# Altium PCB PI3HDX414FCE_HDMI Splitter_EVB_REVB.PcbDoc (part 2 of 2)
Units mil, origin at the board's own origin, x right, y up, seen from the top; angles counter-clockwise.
Board outline 3885 x 4772 mil, 4 copper layers (Top Layer, InternalPlane1, InternalPlane2, Bottom Layer); 85 components, 103 nets, 428 pads, 187 vias.
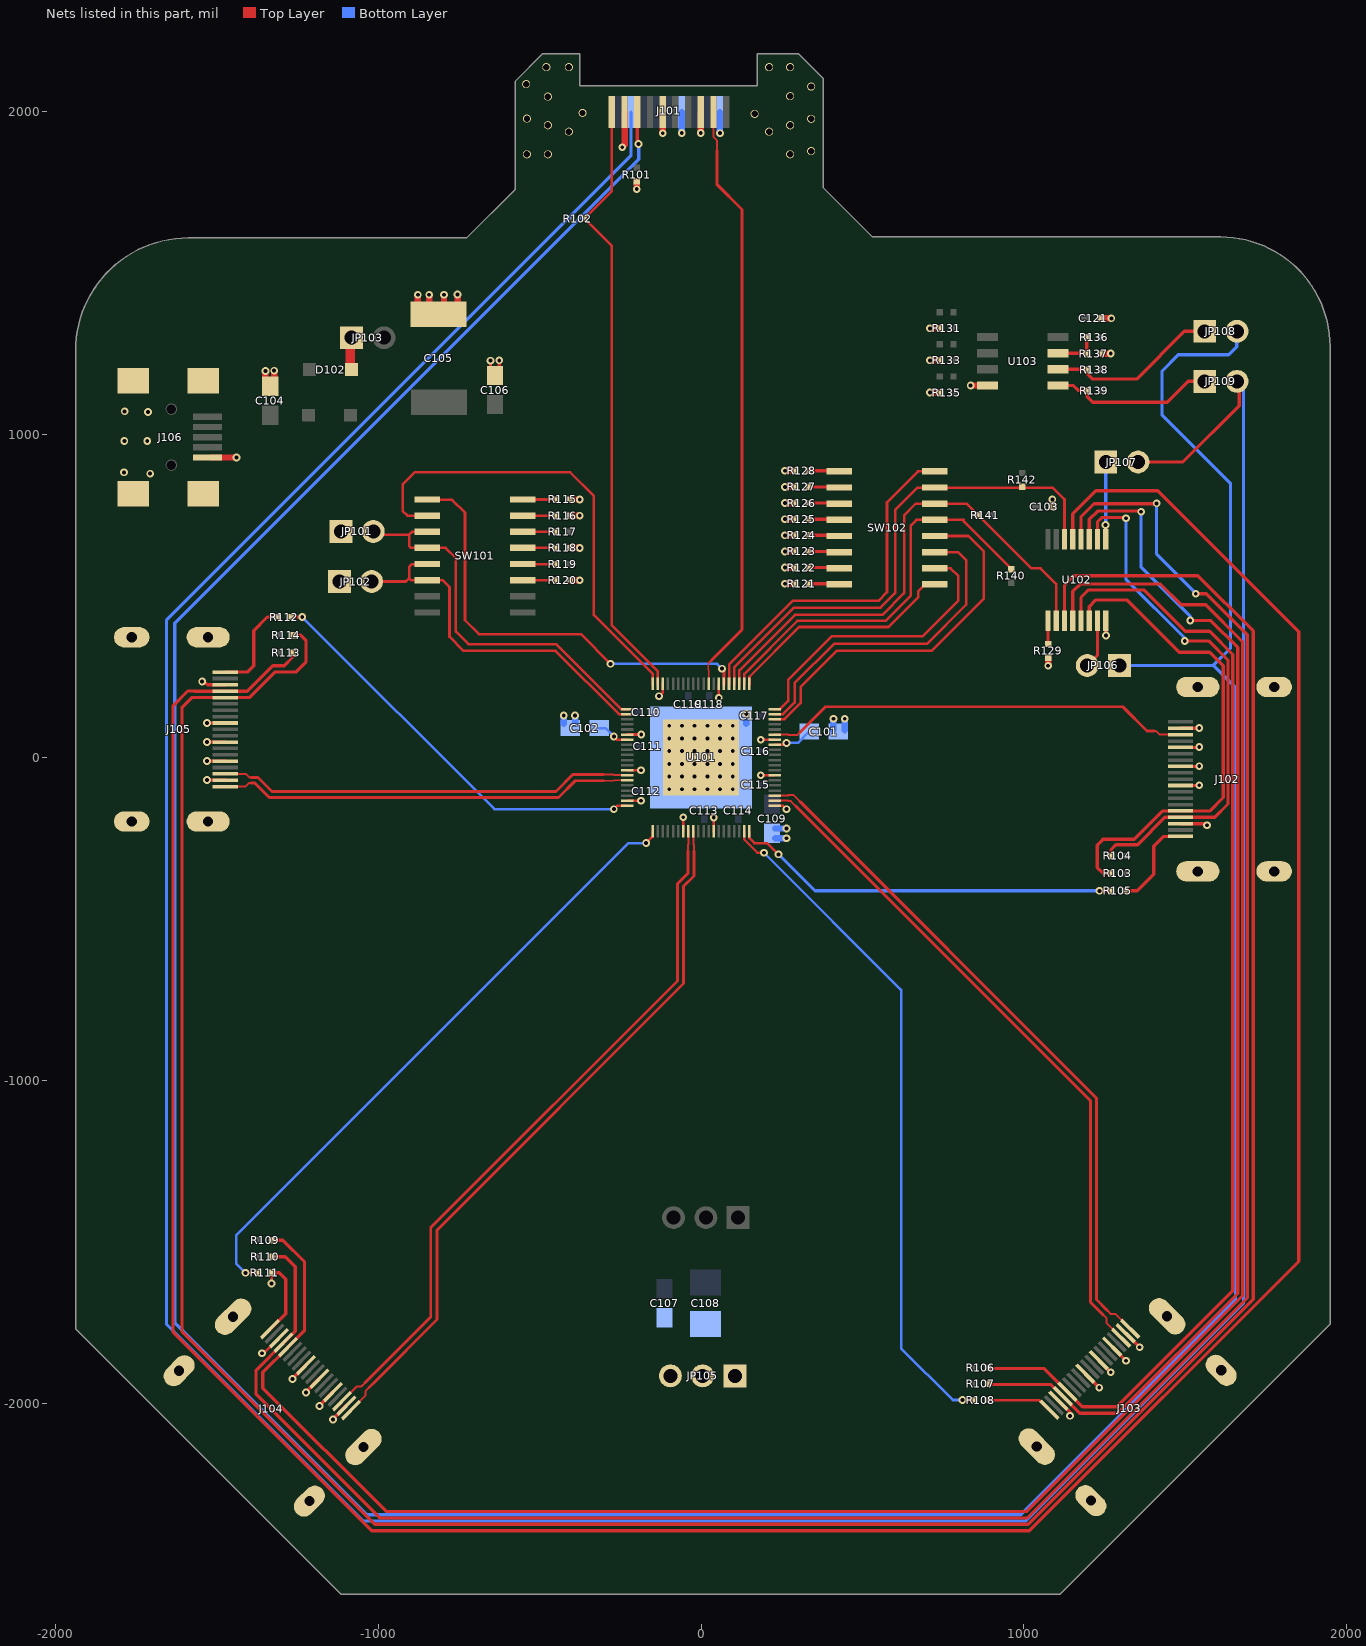
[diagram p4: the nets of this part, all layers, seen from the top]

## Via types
v1: diameter 24, hole 12, Top Layer to Bottom Layer, tented both sides, 186 vias
v2: diameter 35, hole 20, Top Layer to Bottom Layer, tented both sides, 1 vias

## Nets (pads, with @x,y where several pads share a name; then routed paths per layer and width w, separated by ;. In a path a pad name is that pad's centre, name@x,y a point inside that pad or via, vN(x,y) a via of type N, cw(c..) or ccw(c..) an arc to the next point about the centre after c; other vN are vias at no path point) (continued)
D2+_2: J103.1 U101.43 | length 2155.2
  Top Layer w6: U101.43@224.82,-117.72 228.35,-117.72 269.82,-117.72 271.44,-116.09 285.96,-116.09 307.04,-137.17 ; 1258.32,-1712.34 1269.71,-1723.73 1283.73,-1723.73 J103.1@1329.18,-1769.18
  Top Layer w9: 307.04,-137.17 1225,-1055.13 1225,-1679.02 1258.32,-1712.33
D2+_3: J104.1 U101.29 | length 2238
  Top Layer w6: J104.1@-1084.18,-2021.18 -1038.73,-1975.73 -1038.73,-1961.71 -1027.98,-1950.96 ; U101.29@-23.21,-224.02 -23.21,-228.35 -23.21,-269.02 -21.59,-270.64 -21.59,-289
  Top Layer w9: -1027.98,-1950.96 -1007.01,-1929.99 -818,-1740.98 -818,-1463.87 -54,-699.87 -54,-399 -21.59,-366.59 -21.59,-289
D2+_4: J105.1 U101.15 | length 1294.5
  Top Layer w6: J105.1@-1472.94,-90 -1411,-90 -1399.82,-78.82 -1394,-78.82 ; -302.23,-72.1 -270.63,-72.1 -269,-70.47 -228.35,-70.47 U101.15@-224,-70.47
  Top Layer w9: -1394,-78.82 -1382.05,-78.82 -1336.87,-124 -441.13,-124 -389.23,-72.1 -302.23,-72.1
D2-: J101.3 U101.69 | length 1846.1
  Top Layer w6: U101.69@24.03,224.8 24.03,228.35 24.03,269.8 22.41,271.43 22.41,291.28 32.03,300.9 ; J101.3@38,1990 38,1921.98 48.98,1911 48.98,1879
  Top Layer w9: 32.03,300.9 127,395.87 127,1697.13 48.98,1775.15 48.98,1879
D2-_1: J102.3 U101.55 | length 1332.8
  Top Layer w6: U101.55@224.82,71.26 228.35,71.26 269.82,71.26 271.44,69.63 298.5,69.63 305.96,77.09 ; 1403,81.81 1409.19,81.81 1420.37,70.63 J102.3@1484.94,70.63
  Top Layer w9: 305.96,77.09 385.87,157 1306.13,157 1381.32,81.81 1403,81.81
D2-_2: J103.3 U101.42 | length 2137.6
  Top Layer w6: U101.42@224.82,-133.46 228.35,-133.46 269.82,-133.46 271.44,-135.09 278.09,-135.09 293.61,-150.61 ; 1245.57,-1726.46 1256.05,-1736.93 1256.05,-1751.73 J103.3@1301.34,-1797.02
  Top Layer w9: 293.61,-150.61 1206,-1063 1206,-1686.89 1234.06,-1714.94 ; 1235.56,-1716.44 1245.57,-1726.46
D2-_3: J104.3 U101.28 | length 2222.5
  Top Layer w6: J104.3@-1112.02,-1993.34 -1066.73,-1948.05 -1051.93,-1948.05 -1040.45,-1936.56 ; -40.59,-290 -40.59,-270.64 -38.96,-269.02 -38.96,-228.35 U101.28@-38.96,-224.02
  Top Layer w9: -1040.45,-1936.56 -837,-1733.11 -837,-1456 -73,-692 -73,-391.13 -40.59,-358.72 -40.59,-290
D2-_4: J105.3 U101.14 | length 1293.7
  Top Layer w6: J105.3@-1472.94,-50.63 -1410.18,-50.63 -1399,-61.81 -1394,-61.81 ; -302.23,-53.1 -270.63,-53.1 -269,-54.72 -228.35,-54.72 U101.14@-224,-54.72
  Top Layer w9: -1394,-61.81 -1372.25,-61.81 ; -1372.25,-61.75 -1329,-105 -449,-105 -397.1,-53.1 -302.23,-53.1
DR: R140.2 SW102.5 U101.62 | length 1253
  Top Layer w8: U101.62@134.27,224.8 134.27,228.35 134.27,259.27 298,423 572,423 650,501 650,719 667,736 814,736 814,730.3 R140.2@961.03,583.27
EMP1/I2C_ADR2: SW102.2 U101.60 | length 905.1
  Top Layer w8: U101.60@224.82,150 228.35,150 245,150 270,175 270,240 406,376 687,376 797,486 797,562 773,586 SW102.2@727.25,586
EMP2/I2C_ADR3: SW102.1 U101.61 | length 731.5
  Top Layer w8: U101.61@150.02,224.8 150.02,228.35 150.02,250.02 304,404 580,404 672.12,496.12 672.12,514.12 694,536 SW102.1@727.25,536
EQ1/SDA_CTL: JP102.2 SW101.5 SW101.6 U101.2 | length 1159.7
  Top Layer w8: JP102.2@-1020,545 -914,545 -904,555 ; SW101.5@-847.64,599 -895,599 -904,590 -904,555 ; U101.2@-224,134.25 -228.35,134.25 -254.25,134.25 -450,330 -735,330 -779,374 -779,528 -800,549 -898,549 -904,555
EQ2/SCL_CTL: JP101.2 SW101.3 SW101.4 U101.1 | length 1232.4
  Top Layer w8: JP101.2@-1015,700 -1005,690 -904,690 ; SW101.3@-847.64,699 -895,699 -904,690 ; U101.1@-224,150 -228.35,150 -248.43,150 -449.43,351 -720,351 -759,390 -759,617 -791,649 -898,649 -904,655 -904,690
GND: C101.1 C102.1 C103.2 C104.2 C105.2 C106.2 C107.2 C108.2 C109.2 C110.2 C111.2 C112.2 C113.2 C114.2 C115.2 C116.2 C117.2 C118.2 C119.2 C121.2 J101.2 J101.5 J101.8 J101.11 J101.17 J101.20 J102.2 J102.5 J102.8 J102.11 J102.17 J102.20 J102.21 J102.22 J102.23 J103.2 J103.5 J103.8 J103.11 J103.17 J103.20 J103.21 J103.22 J103.23 J104.2 J104.5 J104.8 J104.11 J104.17 J104.20 J104.21 J104.22 J104.23 J105.2 J105.5 J105.8 J105.11 J105.17 J105.20 J105.21 J105.22 J105.23 J106.5 JP101.1 JP102.1 JP105.1 JP105.2 JP105.3 pad.81 R101.2 R115.2 R116.2 R118.2 R120.2 R121.2 R122.2 R123.2 R124.2 R125.2 R126.2 R127.2 R128.2 R129.1 R131.1 R133.1 R135.1 R137.1 U101.6 U101.13 U101.19 U101.27 U101.33 U101.41 U101.47 U101.54 U101.67 U101.78 U101.81 U102.8 U103.4 | length 3599.9
  Top Layer w8: v1(-1360,-1845) -1353.42,-1845 J104.17@-1306.89,-1798.47 ; U101.19@-228.35,-133.86 v1(-186.14,-133.86) ; U101.13@-228.35,-39.37 v1(-185.63,-39.37) ; U101.6@-228.35,71.26 v1(-185,71.26) ; v1(-130,190) -118.11,201.89 U101.78@-118.11,228.35 ; U101.27@-55.12,-228.35 v1(-55.12,-185.12) ; U101.33@39.37,-228.35 v1(39.37,-185.63) ; v1(55.12,185.12) U101.67@55.12,228.35 ; v1@185,55.51 U101.54@228.35,55.51 ; v1(185.12,-55.12) U101.47@228.35,-55.12 ; U101.41@228.35,-149.61 254.61,-149.61 v1(265,-160)
  Top Layer w10: -1532,229 -1527.96,224.96 J105.17@-1472.94,224.96 ; v1(-1530,-70) J105.2@-1472.94,-70 ; v1(-1530,-10.94) J105.5@-1472.94,-10.94 ; v1(-1530,48.11) J105.8@-1472.94,48.11 ; v1(-1530,107.17) J105.11@-1472.94,107.17 ; v1@-1266.27,-1923.73 -1223.95,-1881.4 J104.11@-1223.37,-1880.82 ; v1@-1224.52,-1965.48 -1182.19,-1923.16 -1181.61,-1922.58 J104.8@-1181.61,-1923.74 ; J104.11@-1223.37,-1881.98 J104.11@-1223.37,-1881.37 ; v1@-1182.76,-2007.24 -1140.44,-1964.92 J104.5@-1139.86,-1964.34 ; v1@-1141,-2049 -1098.68,-2006.68 -1098.1,-2006.1 J104.2@-1098.1,-2007.26 ; J104.5@-1139.86,-1965.5 J104.5@-1139.86,-1964.86 ; C105.2@-807,1391 C105.2@-796,1402 ; C106.2@-652,1186 v1(-652,1229.02) ; C106.2@-625,1185 v1(-625,1230.02) ; v1(259.72,588.03) R122.2@290.73,588.03 ; v1(259.72,638.03) R123.2@290.73,638.03 ; v1(259.72,688.03) R124.2@290.73,688.03 ; v1(259.72,738.03) R125.2@290.73,738.03 ; v1(259.72,788.03) R126.2@290.73,788.03 ; v1(259.72,838.03) R127.2@290.73,838.03 ; v1(259.72,888.03) R128.2@290.73,888.03 ; C103.2@1088,776 v1(1088,799) ; J103.17@1106.47,-1991.89 1106.89,-1991.89 1143,-2028 v1(1143,-2039) ; J103.11@1189.98,-1907.98 J103.11@1189.98,-1908.37 v1(1233.31,-1951.69) ; J103.8@1231.74,-1866.61 1231.61,-1866.61 1231.68,-1866.68 v1(1268.86,-1903.86) ; U102.8@1253.57,423.86 1253.57,378.43 v1(1254,378) ; J103.5@1273.5,-1824.86 1272.85,-1824.86 1273.18,-1825.18 v1(1316.18,-1868.18) ; J103.2@1315.26,-1783.1 1315.1,-1783.1 1315.18,-1783.18 v1(1358.42,-1826.42) ; J102.17@1484.94,-204.96 1561.96,-204.96 v1(1567,-210) ; J102.11@1484.94,-86.85 v1@1543,-86.85 ; J102.8@1484.94,-27.8 v1@1543,-27.8 ; J102.5@1484.94,31.26 v1@1543,31.26 ; J102.2@1484.94,90.32 v1@1543,90.32
  Top Layer w19.68: J106.5@-1517.1,929.01 v1(-1438.99,929.01) v1@-1438,930
  Top Layer w20: C104.2@-1349,1154 v1(-1349,1197.02) ; C104.2@-1322,1153 v1(-1322,1198.02) ; C105.2@-877,1377 v1(-877,1433) ; C105.2@-842,1388 v1(-842,1433) ; C105.2@-796,1402 v1(-796,1433) ; C105.2@-754,1395 v1(-754,1434) ; R120.2@-406.73,548.97 v1(-375.72,548.97) ; R118.2@-406.73,648.97 v1(-375.72,648.97) ; R116.2@-406.73,748.97 v1(-375.72,748.97) ; R115.2@-406.73,798.97 v1(-375.72,798.97) ; v1(-244,1890) -236.8,1897.2 J101.17@-236.8,1998.63 ; v1(-199.03,1760.03) R101.2@-199.03,1783.73 ; v1(-118.68,1933.31) J101.11@-118.68,1998.63 ; v1@-1,1935 J101.5@-0.57,1998.63 ; v1(259.72,538.03) R121.2@290.73,538.03 ; v1(259.72,588.03) R122.2@290.73,588.03 ; v1(259.72,638.03) R123.2@290.73,638.03 ; v1(259.72,688.03) R124.2@290.73,688.03 ; v1(259.72,738.03) R125.2@290.73,738.03 ; v1(259.72,788.03) R126.2@290.73,788.03 ; v1(259.72,838.03) R127.2@290.73,838.03 ; v1(259.72,888.03) R128.2@290.73,888.03 ; v1(709.03,1129.97) R135.1@740.05,1129.97 ; v1(709.03,1229.97) R133.1@740.05,1229.97 ; v1(709.03,1328.97) R131.1@740.05,1328.97 ; v1(835,1152) U103.4@886.75,1152 ; v1(1075,284) R129.1@1075.03,309.05 ; R137.1@1237.95,1251.03 v1(1268.97,1251.03) ; C121.2@1239,1360 v1(1270.7,1360)
  Bottom Layer w20: C102.1@-425,105 v1(-425,130) ; C102.1@-390,105 v1(-390,130) ; v1(-59.63,1934.37) J101.8@-59.63,1998.63 ; v1(58.48,1933.52) J101.2@58.48,1998.63 ; pad.81@140,105 C117.2@140,130 v1(140,135) ; C109.2@230,-250 v1(265,-250) ; C109.2@230,-220 v1(265,-220) ; C101.1@410,85 v1(410,120) ; C101.1@445,85 v1(445,120)
  other v1: -1140,-2050 -1181.76,-2008.24 -1223.52,-1966.48 -1265.27,-1924.73 -98.43,-98.43 -59.06,-98.43 -19.68,-98.43 19.68,-98.43 59.06,-98.43 98.43,-98.43 1543,-86 -98.43,-59.06 -59.06,-59.06 -19.68,-59.06 19.68,-59.06 59.06,-59.06 98.43,-59.06 1543,-26.94 -98.43,-19.68 -59.06,-19.68 -19.68,-19.68 19.68,-19.68 59.06,-19.68 98.43,-19.68 -98.43,19.68 -59.06,19.68 -19.68,19.68 19.68,19.68 59.06,19.68 98.43,19.68 1543,32.11 185,55 -98.43,59.06 -59.06,59.06 -19.68,59.06 19.68,59.06 59.06,59.06 98.43,59.06 1543,91.17 -98.43,98.43 -59.06,98.43 -19.68,98.43 19.68,98.43 59.06,98.43 98.43,98.43 -1545,235 -1706,879 -1787,883 -1786,980 -1715,980 -1713,1070 -1785,1072 -1,1934.37
HPD: J101.19 R102.1 U101.79 | length 1904.4
  Top Layer w8: J101.19@-276.17,1998.63 -276.17,1753.91 R102.1@-361.05,1669.03 -277,1584.98 -277,410 -133.45,266.45 -133.45,228.35 U101.79@-133.45,224.8
  Top Layer w10: J101.19@-277,1997.8 J101.19@-276.17,1998.63
HPD_1: J102.19 R105.1 | length 293.8
  Top Layer w10: R105.1@1311.95,-412.97 1351.03,-412.97 1402,-362 1402,-275 1432.67,-244.33 J102.19@1484.94,-244.33
HPD_2: J103.19 R108.1 | length 203.6
  Top Layer w8: R108.1@886.91,-1991 1048,-1991 1076.73,-2019.73 J103.19@1078.63,-2019.73
HPD_3: J104.19 R111.1 | length 257.9
  Top Layer w8: R111.1@-1330.05,-1595.97 R111.1@-1330.05,-1595.97 v1(-1330,-1629)
  Top Layer w10: J104.19@-1334.73,-1770.63 -1333.63,-1770.63 -1286,-1723 -1286,-1616 -1306.03,-1595.97 R111.1@-1327.05,-1595.97
HPD_4: J105.19 R112.2 | length 296.1
  Top Layer w10: J105.19@-1472.94,264.33 -1404.87,264.33 -1385,284.2 -1385,393 -1342.97,435.03 R112.2@-1311.27,435.03
MS: SW101.1 U101.66 | length 1377.7
  Top Layer w8: SW101.1@-848.25,798 -771,798 -731,758 -731,425 -688,382 -372,382 v1(-280,290) ; v1(65,275) 71.28,268.72 71.28,228.35 U101.66@71.28,224.8
  Bottom Layer w8: v1(-280,290) 50,290 v1(65,275)
NetC101_2: C101.2 U101.53 | length 123.5
  Top Layer w8: U101.53@228.35,39.37 259.37,39.37 v1(265,45)
  Bottom Layer w8: v1(265,45) 300,45 C101.2@335,80
NetC102_2: C102.2 U101.7 | length 101.5
  Top Layer w8: v1(-270,65) -260.12,55.12 U101.7@-228.35,55.12
  Bottom Layer w8: C102.2@-315,91 -296,91 v1(-270,65)
NetD102_2: D102.2 JP103.1 | length 99
  Top Layer w30: D102.2@-1086,1201 JP103.1@-1086,1300
NetR105_2: R105.2 U101.40 | length 1209.1
  Top Layer w8: U101.40@149.61,-228.35 149.61,-249.61 165,-265 205,-265 v1(240,-300)
  Top Layer w10: v1(1234,-413) R105.2@1269.73,-412.97
  Bottom Layer w10: v1(240,-300) 353,-413 v1(1234,-413)
NetR108_2: R108.2 U101.39 | length 2107.2
  Top Layer w8: U101.39@133.86,-228.35 133.86,-253.86 175,-295 v1(195,-295)
  Top Layer w10: v1@809,-1991 v1(810.06,-1989.94) R108.2@844.69,-1989.94
  Bottom Layer w8: v1(195,-295) 620,-720 620,-1830 779.94,-1989.94 v1(810.06,-1989.94)
NetR111_2: R111.2 U101.21 | length 1985.1
  Top Layer w8: v1(-1410.97,-1595.97) R111.2@-1372.27,-1595.97 ; v1(-170,-265) -149.61,-244.61 U101.21@-149.61,-228.35
  Bottom Layer w8: v1(-1410.97,-1595.97) -1440,-1566.94 -1440,-1480 -225,-265 v1(-170,-265)
NetR112_1: R112.1 U101.20 | length 1291.5
  Top Layer w8: R112.1@-1269.05,435.03 v1(-1235.03,435.03) ; v1(-270,-160) -259.61,-149.61 U101.20@-228.35,-149.61
  Bottom Layer w8: v1(-1235.03,435.03) -640,-160 v1(-270,-160)
NetR115_1: R115.1 SW101.16 | length 103.4
  Top Layer w8: SW101.16@-552.36,799 R115.1@-448.95,798.97
NetR116_1: R116.1 SW101.15 | length 103.4
  Top Layer w8: SW101.15@-552.36,749 R116.1@-448.95,748.97
NetR117_1: R117.1 SW101.14 | length 103.4
  Top Layer w8: SW101.14@-552.36,699 R117.1@-448.95,698.97
NetR118_1: R118.1 SW101.13 | length 103.4
  Top Layer w8: SW101.13@-552.36,649 R118.1@-448.95,648.97
NetR119_1: R119.1 SW101.12 | length 103.4
  Top Layer w8: SW101.12@-552.36,599 R119.1@-448.95,598.97
NetR120_1: R120.1 SW101.11 | length 103.4
  Top Layer w8: SW101.11@-552.36,549 R120.1@-448.95,548.97
NetR121_1: R121.1 SW102.16 | length 99.8
  Top Layer w10: R121.1@332.95,538.03 SW102.16@432.75,538
NetR122_1: R122.1 SW102.15 | length 99.8
  Top Layer w10: R122.1@332.95,588.03 SW102.15@432.75,588
NetR123_1: R123.1 SW102.14 | length 99.8
  Top Layer w10: R123.1@332.95,638.03 SW102.14@432.75,638
NetR124_1: R124.1 SW102.13 | length 99.8
  Top Layer w10: R124.1@332.95,688.03 SW102.13@432.75,688
NetR125_1: R125.1 SW102.12 | length 99.8
  Top Layer w10: R125.1@332.95,738.03 SW102.12@432.75,738
NetR126_1: R126.1 SW102.11 | length 99.8
  Top Layer w10: R126.1@332.95,788.03 SW102.11@432.75,788
NetR127_1: R127.1 SW102.10 | length 99.8
  Top Layer w10: R127.1@332.95,838.03 SW102.10@432.75,838
NetR128_1: R128.1 SW102.9 | length 99.8
  Top Layer w10: R128.1@332.95,888.03 428.36,888 SW102.9@432.75,888
NetR129_2: R129.2 U102.1 | length 72.8
  Top Layer w10: U102.1@1074.43,423.86 1074.43,351.87 R129.2@1075.03,351.27
OE: SW102.8 U101.65 | length 1114
  Top Layer w8: U101.65@87.02,224.8 87.02,228.35 87.02,288.02 284,485 549,485 576,512 576,790 672,886 SW102.8@727.25,886
ROUT_SEL: SW101.2 U101.80 | length 1463.1
  Top Layer w8: SW101.2@-847.64,749 -909,749 -924,764 -924,846 -887,883 -405,883 -332,810 -332,441 -149.2,258.2 -149.2,228.35 U101.80@-149.2,224.8
SCL: J101.15 JP106.1 JP108.2 | length 11767.6
  Top Layer w10: J101.15@-197.43,1998.63 -197.43,1903.43 v1(-194,1900)
  Bottom Layer w10: v1@-193,1900 -193,1853 -1630,416 -1630,-1750 -1035,-2345 990,-2345 1655,-1680 1655,217 1587,285 ; JP106.1@1296,285 1586,285 1640,339 1640,848 1428,1060 1428,1197 1478,1247 1634,1247 1659,1272 JP108.2@1659,1320
SCL_1: J102.15 R103.1 U102.6 | length 1531.5
  Top Layer w10: U102.6@1202.39,423.86 1202.39,467.39 1223,488 1319,488 1480.88,326.12 ; 1243,-253 1342,-253 1429,-166 1484.94,-166 J102.15@1485.35,-166 ; 1244.5,-254.5 1227,-272 1227,-341 1245.03,-359.03 R103.1@1270.05,-359.03 ; 1480.75,326 1575,326 1617,284 1617,-124 1575,-166 J102.15@1485.35,-166 ; J102.15@1484.94,-165.59 J102.15@1485.35,-166
SCL_2: J103.15 R106.1 U102.5 | length 3562.7
  Top Layer w10: R106.1@887.91,-1891.97 1061.97,-1891.97 1134.05,-1964.05 J103.15@1134.31,-1964.05 1181.26,-2011 1288,-2011 1647,-1652 1647,319 1575,391 1499,391 1371,519 1200,519 1176.8,495.8 U102.5@1176.8,423.86
SCL_3: J104.15 R109.1 U102.4 | length 6767.9
  Top Layer w10: R109.1@-1329.05,-1494.97 -1295.03,-1494.97 -1228,-1562 -1228,-1776 -1228.74,-1776 J104.15@-1279.05,-1826.31 -1357,-1904.26 -1357,-1953 -975,-2335 1009,-2335 1677,-1667 1677,359 1563,473 1487,473 1423,537 1174,537 1151.2,514.2 U102.4@1151.2,423.86
SCL_4: J105.15 R114.2 U102.3 | length 9189.3
  Top Layer w10: R114.2@-1263.73,378.97 -1239.97,378.97 -1223,362 -1223,297 -1255.41,264.59 -1320.41,264.59 -1399.41,185.59 J105.15@-1472.94,185.59 -1577.41,185.59 -1607,156 -1607,-1778 -1010,-2375 1013,-2375 1710,-1678 1710,392 1539,563 1155,563 1125.61,533.61 U102.3@1125.61,423.86
SCL_EEPROM: JP108.1 R138.1 U103.6 | length 536.5
  Top Layer w10: U103.6@1105.25,1202 1195.02,1202 R138.1@1196.05,1200.97 1196.05,1188.95 1213,1172 1349,1172 1497,1320 JP108.1@1560,1320 JP108.1@1561,1320
SCL_SW: JP106.2 U102.7 | length 152.1
  Top Layer w10: JP106.2@1196,285 1227.98,316.98 U102.7@1227.98,423.86
SDA: J101.16 JP107.2 JP109.2 | length 11538
  Top Layer w10: JP107.2@1353.57,915 1492.57,915 1666.57,1089 JP109.2@1666.57,1162
  Bottom Layer w10: J101.16@-217.11,1998.63 -217.11,1863.89 -1655,426 -1655,-1756 -1046,-2365 1005,-2365 1680,-1690 1680,1146 JP109.2@1661,1165
SDA_1: J102.16 R104.1 U102.10 | length 1646.9
  Top Layer w10: U102.10@1227.98,676.14 1227.98,729.98 1241,743 v1@1316,743 ; R104.1@1270.05,-305.03 1270.05,-284.95 1284.94,-270.06 1351.94,-270.06 1436.72,-185.28 J102.16@1484.94,-185.28 1590.72,-185.28 1632,-144 1632,301 1572,361 v1(1498,361)
  Bottom Layer w10: v1(1316,741) 1316,552 1498,370 v1(1498,361)
SDA_2: J103.16 R107.1 U102.11 | length 3779.5
  Top Layer w10: R107.1@887.91,-1941.97 1083.97,-1941.97 1119.97,-1977.97 J103.16@1120.39,-1977.97 1173.42,-2031 1291,-2031 1662,-1660 1662,341 1579,424 v1(1515,424) ; U102.11@1202.39,676.14 1202.39,737.39 1228,763 v1@1363,763
  Bottom Layer w10: v1(1363,761) 1363,589 1515,437 v1(1515,424)
SDA_3: J104.16 R110.1 U102.12 | length 6957.3
  Top Layer w10: R110.1@-1328.05,-1545.97 R110.1@-1328.05,-1545.97 -1287.98,-1546.02 -1257,-1577 -1257,-1777 -1292.39,-1812.39 J104.16@-1292.97,-1812.39 -1378,-1897.42 -1378,-1972 -995,-2355 1011,-2355 1692,-1674 1692,380 1565,507 v1(1532,507) ; U102.12@1176.8,676.14 1176.8,745.8 1217,786 v1@1411,786
  Bottom Layer w10: v1(1411,787) 1411,630 1532,509 v1(1532,507)
SDA_4: J105.16 R113.2 U102.13 | length 9412.6
  Top Layer w10: R113.2@-1263.73,323.97 -1263.73,311.27 -1290.72,284.28 -1325.72,284.28 -1404.72,205.28 J105.16@-1472.94,205.28 -1568.28,205.28 -1569,206 -1589,206 -1635,160 -1635,-1780 -1020,-2395 1017,-2395 1851,-1561 1851,390 1415,826 1223,826 1151.2,754.2 U102.13@1151.2,676.14
SDA_EEPROM: JP109.1 R139.1 U103.5 | length 515.4
  Top Layer w10: U103.5@1105.25,1152 1153,1152 1168,1137 1195.02,1137 R139.1@1196.05,1135.97 1196.05,1116.95 1213,1100 1444,1100 1509,1165 JP109.1@1560,1165 JP109.1@1561,1165
SDA_SW: JP107.1 U102.9 | length 239.7
  Top Layer w10: v1(1253,720) 1253.57,719.43 U102.9@1253.57,676.14
  Bottom Layer w10: v1@1253.57,719.43 1253.57,720 JP107.1@1253.57,915
SEL1_S0: R142.2 SW102.7 U101.64 U102.14 | length 1596.6
  Top Layer w8: U101.64@102.77,224.8 102.77,228.35 102.77,278.77 288,464 556,464 601,509 601,766 671,836 994.97,836 1089,836 1125.61,799.39 U102.14@1125.61,676.14
SEL2_S1: R141.2 SW102.6 U101.63 U102.2 | length 1598.2
  Top Layer w8: U101.63@118.52,224.8 118.52,228.35 118.52,269.52 291,442 562,442 629,509 629,750 665,786 822.76,786 R141.2@858.73,750.03 1022.76,586 1052,586 1100.02,537.98 U102.2@1100.02,423.86
SW1/I2C_ADR0: SW102.4 U101.58 | length 1152.6
  Top Layer w8: U101.58@224.82,118.5 228.35,118.5 258.5,118.5 308.45,168.45 308.45,218.45 421,331 715,331 875,491 875,639 828,686 SW102.4@723.64,686
SW2/I2C_ADR1: SW102.3 U101.59 | length 1017.4
  Top Layer w8: U101.59@224.82,134.25 228.35,134.25 254.25,134.25 290,170 290,230 412,352 700,352 821,473 821,611 796,636 SW102.3@723.64,636
WP: R136.1 R137.2 U103.7 | length 140.4
  Top Layer w10: U103.7@1105.25,1252 R137.2@1194.76,1252 ; R137.2@1195.73,1251.03 R137.2@1194.76,1252 ; R136.1@1196.05,1300.97 1194.76,1299.69 R137.2@1194.76,1252
pads on no net: J101.14 J102.14 J103.14 J104.14 J105.14 J106.2 J106.3 J106.4 J106.10 J106.11 SW101.7 SW101.8 SW101.9 SW101.10 U102.15

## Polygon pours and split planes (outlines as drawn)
+5V_USB on Top Layer "Bottom Layer-No Net" (solid, remove dead copper, pour order 1000): -1579,1040 -1579,1105 -1164,1105 -1164,980 -1404,980 -1454,1030 -1464,1040 -1579,1040
+5V on Top Layer "Bottom Layer-No Net" (solid, pour order 1000): -1111,1131 -1110,1132 -1008,1132 -1008,1334 -1006,1336 -1005,1337 -959,1337 -959,1139 -961,1137 -960,1138 -696,1138 -696,1132 -692,1128 -687,1123 -583,1123 -583,1021 -584,1020 -1111,1020 -1111,1131
GND on Bottom Layer "Bottom Layer-No Net" (solid, pour order 1002): -156,-1709 186,-1709 187,-1708 187,-2009 186,-2010 -156,-2010 -156,-1709
+3V3 on Bottom Layer "Bottom Layer-No Net" (solid, pour order 1001): -157,-1355 -156,-1354 185,-1354 185,-1677 184,-1676 -157,-1676 -157,-1355
GND on InternalPlane1 (split plane): 358.61,2093.55 358.61,1764 360.16,1756.2 364.58,1749.58 516.58,1597.58 523.2,1593.16 531,1591.61 1608.86,1591.61 1609.03,1591.57 1610.15,1591.8 1640.29,1590.31 1671.24,1585.72 1701.59,1578.12 1731.05,1567.58 1759.34,1554.2 1786.18,1538.11 1811.31,1519.47 1834.5,1498.46 1855.51,1475.28 1874.15,1450.14 1890.23,1423.3 1903.61,1395.02 1914.15,1365.56 1921.76,1335.2 1926.35,1304.25 1927.83,1274.11 1927.61,1273 1927.61,-1746.55 1102.55,-2571.61 -1105.55,-2571.61 -1254.58,-2422.58 -1916.61,-1760.55 -1916.61,1260 -1916.84,1261.16 -1915.31,1292.23 -1910.58,1324.16 -1902.74,1355.46 -1891.86,1385.85 -1878.06,1415.02 -1861.47,1442.71 -1842.25,1468.63 -1820.57,1492.54 -1796.66,1514.21 -1770.74,1533.44 -1743.06,1550.03 -1713.88,1563.83 -1683.5,1574.7 -1652.19,1582.54 -1620.27,1587.28 -1589.19,1588.81 -1588.03,1588.57 -1587.86,1588.61 -726,1588.61 -718.2,1590.16 -711.58,1594.58 -560.58,1745.58 -557.93,1749.55 -556.16,1752.2 -554.61,1760 -554.61,2086.55 -481.55,2159.61 -395.39,2159.61 -395.39,2080 -393.84,2072.2 -389.42,2065.58 -382.8,2061.16 -375,2059.61 174,2059.61 181.8,2061.16 188.42,2065.58 192.84,2072.2 194.39,2080 194.39,2159.61 292.55,2159.61
+3V3 on InternalPlane2 (split plane): 358.61,2093.55 358.61,1764 360.16,1756.2 364.58,1749.58 516.58,1597.58 520.8,1594.76 520.8,1124 521.58,1120.1 523.79,1116.79 637.79,1002.79 641.1,1000.58 645,999.8 1470.78,999.8 1624.8,845.78 1624.8,-115.78 1585.78,-154.8 1415,-154.8 1411.1,-155.58 1407.79,-157.79 1272.79,-292.79 1270.58,-296.1 1269.8,-300 1269.8,-445 1270.58,-448.9 1272.79,-452.21 1519.8,-699.22 1519.8,-1760.78 1268.17,-2012.41 1191.83,-2012.41 1007.21,-1827.79 1003.9,-1825.58 1000,-1824.8 780,-1824.8 776.1,-1825.58 772.79,-1827.79 395.78,-2204.8 -1075.78,-2204.8 -1333.29,-1947.29 -1333.29,-1892.71 -1232.79,-1792.21 -1230.58,-1788.9 -1229.8,-1785 -1229.8,-1595 -1230.58,-1591.1 -1232.79,-1587.79 -1614.8,-1205.78 -1614.8,133.78 -1558.78,189.8 -1335,189.8 -1331.1,190.58 -1327.79,192.79 -912.79,607.79 -910.58,611.1 -909.8,615 -909.8,655.78 -497.79,1067.79 -495.58,1071.1 -494.8,1075 -494.8,1388 -495.58,1391.9 -497.79,1395.21 -704.37,1601.79 -560.58,1745.58 -557.93,1749.55 -556.16,1752.2 -554.61,1760 -554.61,2086.55 -481.55,2159.61 -395.39,2159.61 -395.39,2080 -393.84,2072.2 -389.42,2065.58 -382.8,2061.16 -375,2059.61 174,2059.61 181.8,2061.16 188.42,2065.58 192.84,2072.2 194.39,2080 194.39,2159.61 292.55,2159.61
+5V on InternalPlane2 (split plane): 1640.29,1590.31 1671.24,1585.72 1701.59,1578.12 1731.05,1567.58 1759.34,1554.2 1786.18,1538.11 1811.31,1519.47 1834.5,1498.46 1855.51,1475.28 1874.15,1450.14 1890.23,1423.3 1903.61,1395.02 1914.15,1365.56 1921.76,1335.2 1926.35,1304.25 1927.83,1274.11 1927.61,1273 1927.61,-1746.55 1102.55,-2571.61 -1105.55,-2571.61 -1254.58,-2422.58 -1916.61,-1760.55 -1916.61,1260 -1916.84,1261.16 -1915.31,1292.23 -1910.58,1324.16 -1902.74,1355.46 -1891.86,1385.85 -1878.06,1415.02 -1861.47,1442.71 -1842.25,1468.63 -1820.57,1492.54 -1796.66,1514.21 -1770.74,1533.44 -1743.06,1550.03 -1713.88,1563.83 -1683.5,1574.7 -1652.19,1582.54 -1620.27,1587.28 -1589.19,1588.81 -1588.03,1588.57 -1587.86,1588.61 -726,1588.61 -721.02,1589.6 -515.2,1383.78 -515.2,1079.22 -927.21,667.21 -929.42,663.9 -930.2,660 -930.2,619.22 -1339.22,210.2 -1563,210.2 -1566.9,209.42 -1570.21,207.21 -1632.21,145.21 -1634.42,141.9 -1635.2,138 -1635.2,-1210 -1634.42,-1213.9 -1632.21,-1217.21 -1250.2,-1599.22 -1250.2,-1780.78 -1350.69,-1881.27 -1352.9,-1884.58 -1353.68,-1888.48 -1353.68,-1951.52 -1352.9,-1955.42 -1350.69,-1958.73 -1087.21,-2222.21 -1083.9,-2224.42 -1080,-2225.2 400,-2225.2 403.9,-2224.42 407.21,-2222.21 784.22,-1845.2 995.78,-1845.2 1180.4,-2029.82 1183.7,-2032.03 1187.61,-2032.8 1272.39,-2032.8 1276.3,-2032.03 1279.6,-2029.82 1537.21,-1772.21 1539.42,-1768.9 1540.2,-1765 1540.2,-695 1539.42,-691.1 1537.21,-687.79 1290.2,-440.78 1290.2,-304.22 1419.22,-175.2 1590,-175.2 1593.9,-174.42 1597.21,-172.21 1642.21,-127.21 1644.42,-123.9 1645.2,-120 1645.2,850 1644.42,853.9 1642.21,857.21 1482.21,1017.21 1478.9,1019.42 1475,1020.2 649.22,1020.2 541.2,1128.22 541.2,1591.61 1608.86,1591.61 1609.03,1591.57 1610.15,1591.8

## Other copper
InternalPlane2 (plane layer: these items are gaps in the copper):
  lines w20: -726,1609 -505,1388 -505,1075 -920,660 -920,615 -1335,200 -1563,200 -1625,138 -1625,-1210 -1240,-1595 -1240,-1785 -1343.48,-1888.48 -1343.48,-1951.52 -1080,-2215 400,-2215 780,-1835 1000,-1835 1187.61,-2022.61 1272.39,-2022.61 1530,-1765 1530,-695 1280,-445 1280,-300 1415,-165 1590,-165 1635,-120 1635,850 1475,1010 645,1010 531,1124 531,1612

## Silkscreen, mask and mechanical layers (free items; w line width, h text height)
Top Overlay:
  lines w3.94: -1028,800 -900,710 ; -1020,860 -898.03,757.34 ; -985,435 -895,535 ; 668,421 722,521 ; 783,582 889,466
  text "SCL" at 1730,1301 h60
  text "SDA" at 1730,1140 h60
  text "OE" at 767,891 h50
  text "SDA" at 1425,865 h60
  text "ROUT_SEL" at -1301,861 h60
  text "MS" at -886,858 h60
  text "SEL_S0" at 765,849 h50
  text "SEL2_S1" at 771,789 h50
  text "EQ2/SCL_CTL" at -1373,781 h60
  text "DR" at 772,715 h50
  text "SW1/I2C-ADR0" at 765,670 h50
  text "SW2/I2C-ADR1" at 765,630 h50
  text "EMP1/I2C-ADR2" at 708,426 h50
  text "EQ1/SDA_CTL" at -1200,390 h60
  text "EMP2/I2C-ADR3" at 630,376 h50
  text "SCL" at 1360,316 h60
  text "+3.3V" at 230,-1440 h60
  text "GND" at 225,-1935 h60
Bottom Overlay:
  rectangle: -300,-1295 407,-1096.5
  text "PI3HDX414FCE_HDMI SW_EVB" at 540,-1002 h60
  text "REV.B" at 91,-1072 h60
  text "Date:2014.5.22" at 536,-1072 h60
  text "S/N:" at 524,-1194 h60
  text "1423DB278" at 905,-2560 h60
Mechanical 1:
  lines w3.94: -1937,1260 -1937,-1769 -1269,-2437 -1114,-2592 1111,-2592 1948,-1755 1948,1273 ; -1588,1609 -728,1609 ; -575,1760 -575,2095 -490,2180 -375,2180 -375,2080 174,2080 174,2180 301,2180 379,2102 379,1764 ; 532,1612 1609.03,1612
  lines w4: -1937,1260 cw(c-1588.03,1260) -1588.03,1608.97 ; 1609.03,1611.97 cw(c1609.03,1273) 1948,1273
  lines w5: -728,1609 -726,1609 -575,1760 ; 379,1764 531,1612 532,1612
